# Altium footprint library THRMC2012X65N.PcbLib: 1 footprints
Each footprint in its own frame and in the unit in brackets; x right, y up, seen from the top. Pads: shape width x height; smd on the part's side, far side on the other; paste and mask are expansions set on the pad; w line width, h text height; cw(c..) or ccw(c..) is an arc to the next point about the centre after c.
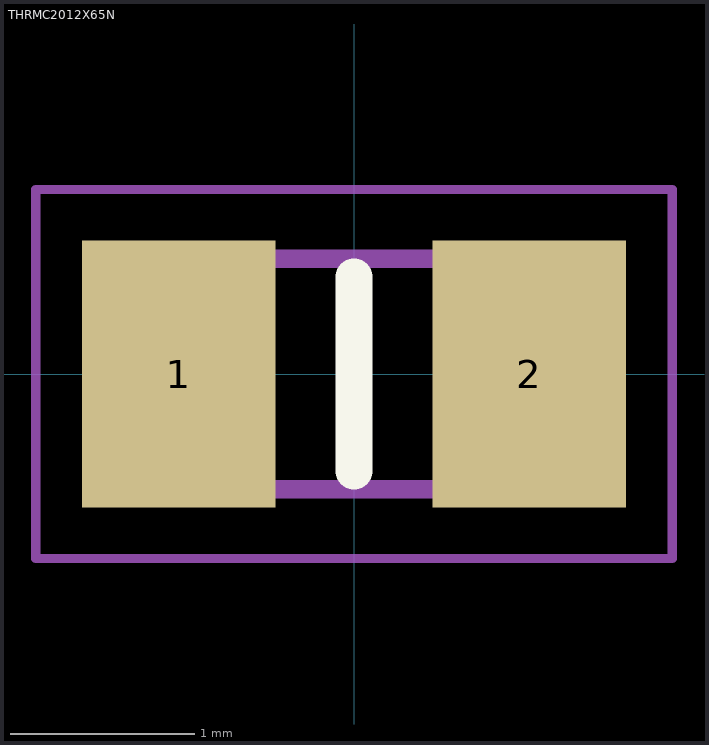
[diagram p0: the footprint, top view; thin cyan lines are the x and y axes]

## THRMC2012X65N [mm]
pads (2):
  rect 1.05x1.45 smd: 1(-0.95,0) 2(0.95,0)
Top Overlay:
  lines w0.2: 0,-0.525 0,0.525
Mechanical 15:
  lines w0.1: -1,-0.625 1,-0.625 1,0.625 -1,0.625 -1,-0.625
Mechanical 20:
  lines w0.05: -1.725,-1 1.725,-1 1.725,1 -1.725,1 -1.725,-1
